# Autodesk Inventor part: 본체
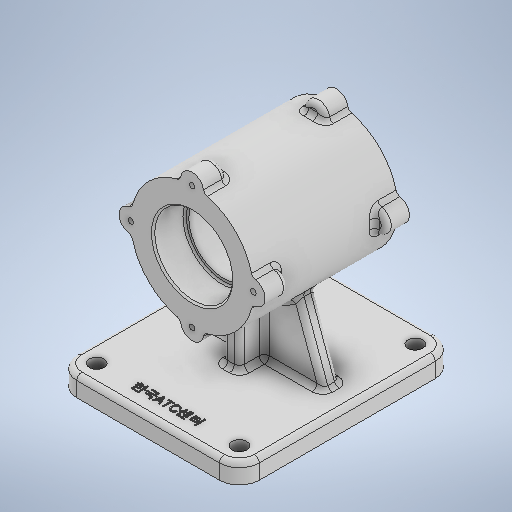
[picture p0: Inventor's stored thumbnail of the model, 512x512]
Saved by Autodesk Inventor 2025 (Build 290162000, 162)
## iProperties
Created: 2024-08
Part Number: 본체
Material: 일반
Document SubType Name: Modeling
Designer: samsung
Density: 1 g/cm^3
Appearance: 기본값
Author: samsung
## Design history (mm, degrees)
sketch "스케치1"
  geometry: L1 (-55, -65)-(55, -65); L2 (55, -65)-(55, 65); L3 (55, 65)-(-55, 65); L4 (-55, 65)-(-55, -65); L5 (-55, -65)-(55, 65); L6 (55, -65)-(-55, 65); 1 further point
  constraints: 12 end point, 2 midpoint, 2 parallel, 1 horizontal, 1 perpendicular
  dimensions: "d0" = 110 distance of L3.end L2.end; "d1" = 130 distance of L2.end L1.end
extrude "돌출1" new body sketch "스케치1" distance "d2" = 12; taper "d3" = 0 deg
node "작업 평면1"
sketch "스케치2"
  geometry: C1 r 37 at (55, 82); 1 further point
  constraints: 1 centre point, 1 vertical alignment
  dimensions: "d5" = 74 diameter of C1; "d6" = 82 distance of point (55, 0) C1.centre
extrude "돌출2" join sketch "스케치2" stored distance "d7" = 87; taper "d8" = 0 deg
sketch "스케치5"
  geometry: C1 r 37 at (0, 0) reference; C2 r 23.5 at (0, 0); 1 further point
  constraints: 1 centre point, 1 coincident
  dimensions: "d23" = 47 diameter of C2
extrude "돌출4" cut sketch "스케치5" distance "d24" = 19; taper "d25" = 0 deg
sketch "스케치6"
  geometry: C1 r 37 at (0, 0) reference; C2 r 23.5 at (0, 0); 1 further point
  constraints: 1 centre point, 1 coincident
  dimensions: "d26" = 47 diameter of C2
extrude "돌출5" cut sketch "스케치6" distance "d27" = 19; taper "d28" = 0 deg
sketch "스케치7"
  geometry: C1 r 23.5 at (0, 0) reference; C2 r 21 at (0, 0); 1 further point
  constraints: 1 centre point, 1 coincident
  dimensions: "d29" = 42 diameter of C2
extrude "돌출6" cut sketch "스케치7" stored distance "d30" = 19; taper "d31" = 0 deg
chamfer "모따기1" distance "d42" = 1; stored, may be unused: second distance "d43" = 2, angle "d44" = 45 deg
fillet "모깎기1" dims "d45" = 12
fillet "모깎기2" dims "d46" = 3
fillet "모깎기3" dims "d47" = 1
sketch "스케치11"
  geometry: L1 (41, 10)-(-41, 10); L2 (-41, 10)-(-41, 0); L3 (-41, 0)-(41, 0); L4 (41, 0)-(41, 10); L5 (41, 10)-(-41, 0); L6 (-41, 10)-(41, 0); L7 (-43, -65)-(43, -65) reference; 2 further points
  constraints: 12 end point, 2 midpoint, 2 parallel, 1 horizontal, 1 perpendicular, 1 vertical alignment
  dimensions: "d63" = 82 distance of L3.end L2.end; "d64" = 10 distance of L2.end L1.end; "d65" = 70 distance from line of L7 point (0, 5)
extrude "돌출8" join sketch "스케치11" distance "d66" = 82; taper "d67" = 0 deg
feature "면 기울기1" dims angle "d68" = 20 deg
sketch "스케치12"
  geometry: L1 (5, 25)-(-5, 25); L2 (-5, 25)-(-5, -15); L3 (-5, -15)-(5, -15); L4 (5, -15)-(5, 25); L5 (5, 25)-(-5, -15); L6 (-5, 25)-(5, -15); L7 (-43, -65)-(43, -65) reference; 2 further points
  constraints: 12 end point, 2 midpoint, 2 parallel, 1 horizontal, 1 perpendicular, 1 vertical alignment
  dimensions: "d69" = 10 distance of L3.end L2.end; "d70" = 40 distance of L2.end L1.end; "d71" = 70 distance from line of L7 point (0, 5)
extrude "돌출9" join sketch "스케치12" distance "d72" = 82; taper "d73" = 0 deg
sketch "스케치13"
  geometry: C1 r 24.5 at (55, 82) reference; C2 r 21 at (55, 82); 1 further point
  constraints: 1 centre point, 1 coincident
  dimensions: "d74" = 42 diameter of C2
extrude "돌출10" cut sketch "스케치13" extent not by distance; stored distance "d75" = 0; taper "d76" = 0 deg
fillet "모깎기4" dims "d77" = 3
fillet "모깎기5" dims "d78" = 3
fillet "모깎기6" dims "d79" = 3
sketch "스케치14"
  geometry: L1 (-43, -65)-(43, -65) reference; L2 (55, -53)-(55, 53) reference; C1 r 4.5 at (43, -53); 1 further point
  constraints: 1 centre point
  dimensions: "d80" = 9 diameter of C1; "d81" = 12 distance from line of L1 C1.centre; "d82" = 12 distance from line of L2 C1.centre
extrude "돌출11" cut sketch "스케치14" stored distance "d83" = 10; taper "d84" = 0 deg
sketch "스케치15"
  geometry: L1 (-43, -65)-(43, -65) reference; 2 further points
  constraints: 1 vertical alignment, 1 other
  dimensions: "d86" = 12 distance from line of L1 point (0, -53)
feature "엠보싱1" sketch "스케치15" dims "d0" = 110, "d1" = 130, "d87" = 0.5, "d88" = 0
sketch "스케치16"
  geometry: C1 r 7 at (37, 0); C2 r 37 at (0, 0) reference; 1 further point
  constraints: 1 centre point, 1 horizontal alignment
  dimensions: "d89" = 14 diameter of C1; "d90" = 37 distance of C1.centre C2.centre
extrude "돌출12" join sketch "스케치16" distance "d91" = 14; taper "d92" = 0 deg
fillet "모깎기8" dims "d96" = 3
fillet "모깎기9" dims "d97" = 3
sketch "스케치17"
  geometry: C1 r 24.5 at (55, 82) reference; A1 r 37 centre (55, 82) between (64.104, 46.138) and (90.862, 72.896) reference; A2 r 3 centre (93.77, 72.158) between (93.239, 75.111) and (90.862, 72.896) reference; A3 r 7 centre (92, 82) between (93.239, 75.111) and (93.239, 88.889) reference; A4 r 3 centre (93.77, 91.842) between (90.862, 91.104) and (93.239, 88.889) reference; A5 r 37 centre (55, 82) between (90.862, 91.104) and (64.104, 117.863) reference; A6 r 3 centre (64.842, 120.77) between (61.889, 120.239) and (64.104, 117.863) reference; A7 r 7 centre (55, 119) between (61.889, 120.239) and (48.111, 120.239) reference; A8 r 3 centre (45.158, 120.77) between (45.896, 117.863) and (48.111, 120.239) reference; A9 r 37 centre (55, 82) between (45.896, 117.863) and (19.137, 91.104) reference; A10 r 3 centre (16.23, 91.842) between (16.761, 88.889) and (19.137, 91.104) reference; A11 r 7 centre (18, 82) between (16.761, 88.889) and (16.761, 75.111) reference; A12 r 3 centre (16.23, 72.158) between (19.137, 72.896) and (16.761, 75.111) reference; A13 r 37 centre (55, 82) between (19.137, 72.896) and (45.896, 46.138) reference; A14 r 3 centre (45.158, 43.23) between (48.111, 43.761) and (45.896, 46.138) reference; A15 r 7 centre (55, 45) between (48.111, 43.761) and (61.889, 43.761) reference; A16 r 3 centre (64.842, 43.23) between (64.104, 46.138) and (61.889, 43.761) reference; 1 further point
hole "구멍2" sketch "스케치17" at (55, 119), (92, 82), (55, 45), (18, 82) diameter "d98" = 3.242; stored, may be unused: countersink angle "d102" = 90 deg, drill point angle "d104" = 118 deg; dims "d99" = 8, "d100" = 4, "d101" = 2, "d103" = 10
node "솔리드1"
mirror "미러3"
mirror "미러4"
pattern_circular "원형 패턴1" dims angle "d94" = 360 deg
mirror "미러5"
mirror "미러7"
node "투영된 루프2"
feature "A9D066F2-1C7D-4E18-AEED-F7BC21143FA4" dims "d98" = 3.242, "d99" = 8, "d100" = 4, "d101" = 2, "d102" = 90 deg, "d103" = 10, "d104" = 118 deg
